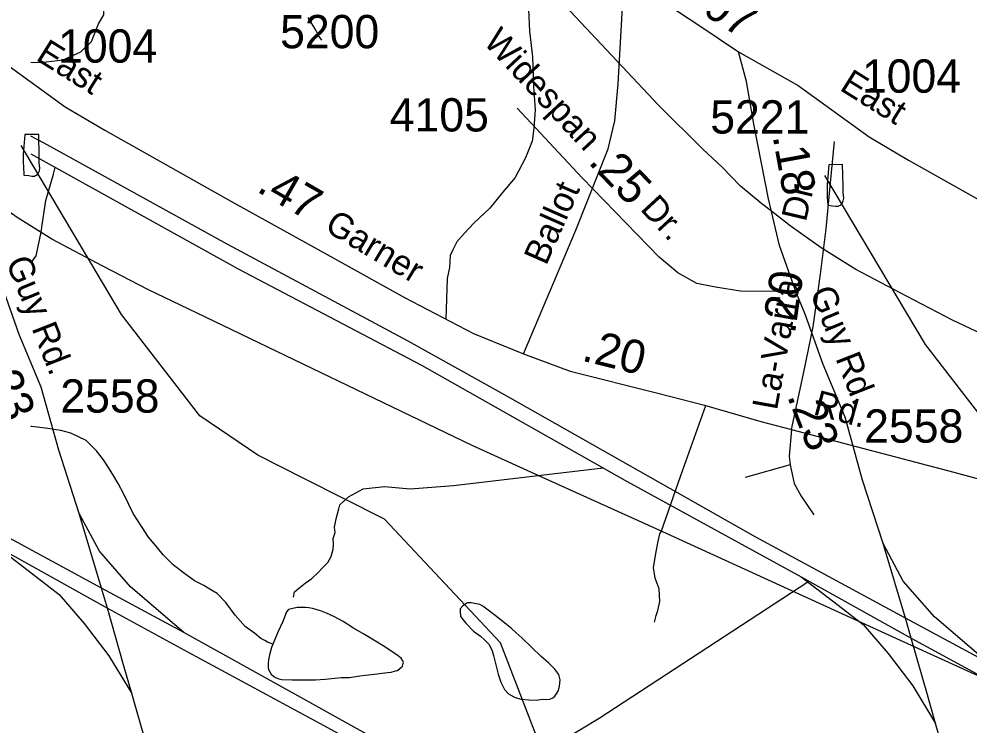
# Model space of a CAD drawing. Extents: x 2169602 to 2449496, y 721995 to 810662.
# Drawn here: x 2382070 to 2385634, y 765731 to 768381 of the extents above; entities that cross this region are included whole.
import ezdxf

# ---------------------------------------------------------------- set-up
doc = ezdxf.new("R2010")
doc.units = 0
doc.layers.add('Default', color=7, linetype='Continuous')

msp = doc.modelspace()

# ---------------------------------------------------------------- linework, layer by layer
at = {"layer": 'Default'}
for p, q in [((2382199.6, 767798.2), (2382205.6, 767824)), ((2384552.9, 766666.8), (2384647, 766929.6)), ((2384478.9, 766456.4), (2384552.9, 766666.8))]:
    msp.add_line(p, q, dxfattribs=at)
for points in [[(2384887.9, 767663.1), (2384856.4, 767687.8), (2384776.2, 767753.4), (2384707.8, 767825), (2384635.4, 767892.7), (2384468.8, 768057.9), (2384099.3, 768452.2), (2383723.7, 768848.4), (2383550.9, 769023.7), (2383458.6, 769117.2), (2383310.1, 769238.4), (2383207.7, 769300.1), (2383101.5, 769365.4), (2383005.3, 769423), (2382875.2, 769486.4), (2382114, 769885.3)], [(2383962.9, 767123.6), (2384159.1, 767588.5), (2384280.5, 767894.3), (2384305.6, 767999), (2384318.2, 768137.2), (2384360, 768891.2), (2384384.1, 769453), (2384383.2, 769500.7)], [(2382114, 768219.7), (2382150.3, 768218), (2382236.2, 768228), (2382302.2, 768257.7), (2382341.9, 768297.3), (2382368.3, 768363.4), (2382388.1, 768396.5), (2382388.1, 768436.1), (2382335.3, 768452.6), (2382206.5, 768495.6), (2382137.1, 768498.9)], [(2383981.2, 768415.7), (2383985.5, 768335.8), (2383996, 768239.8), (2384000.5, 768127.9), (2384006.9, 768040), (2384001.1, 767971.9), (2383995.3, 767922), (2383969.6, 767860), (2383931.9, 767785.7), (2383884.2, 767729.5), (2383836.6, 767671.3), (2383776.8, 767615.1), (2383740.8, 767577.1), (2383713, 767544.8), (2383697.2, 767514.8), (2383687.3, 767492.8), (2383685.4, 767448.8), (2383675.8, 767406.8), (2383671.7, 767254.3)], [(2384504.6, 768434.9), (2384617.1, 768360.5), (2384769.8, 768257.9)], [(2381754, 768370.7), (2381976.9, 768244), (2382243.7, 768051.4), (2382391.8, 767964.5), (2382864.7, 767697.4), (2383248.8, 767484.9), (2383516.6, 767336.2), (2383774.6, 767200.1), (2383962.9, 767123.6)], [(2383205.5, 768301.8), (2383193.6, 768319.8), (2383183.2, 768339.6), (2383155.1, 768387.3)], [(2384769.8, 768257.9), (2384992.7, 768131.2), (2385259.5, 767938.5), (2385407.6, 767851.6), (2385880.6, 767584.6), (2386264.6, 767372), (2386532.5, 767223.3), (2386790.4, 767087.2), (2386978.7, 767010.8)], [(2384893.1, 767659), (2384881.8, 767706.1), (2384827.9, 767980.4), (2384799.6, 768146.9), (2384769.8, 768257.9)], [(2382379.8, 766244.3), (2381818.6, 766548.8), (2380886.3, 767076.6), (2380513.8, 767283.9), (2379835.7, 767648.3), (2379148.2, 768027.4), (2379098.1, 768054.5)], [(2384984.9, 767358.4), (2384776.6, 767359.5), (2384682.5, 767374.1), (2384613.4, 767388.8), (2384542.2, 767428.6), (2384471.1, 767487.2), (2384182.3, 767784.6), (2383939.3, 768046.9)], [(2382136.2, 767795.1), (2382141.9, 767801.1), (2382146.2, 767811), (2382148.3, 767821.3), (2382146, 767843.1), (2382145.8, 767855.3), (2382145.8, 767867.1), (2382143.8, 767947.3), (2382091.9, 767947), (2382085.9, 767872.9), (2382086.1, 767840.8), (2382086.4, 767827), (2382088.2, 767795.1), (2382106.2, 767793.2), (2382118.1, 767790.9), (2382128, 767791.1), (2382132.1, 767793.3), (2382136.2, 767795.1)], [(2385395.6, 766131.5), (2384834.4, 766436), (2383902.1, 766963.8), (2383529.6, 767171.1), (2382851.5, 767535.5), (2382164.1, 767914.6), (2382114, 767941.7)], [(2383141.1, 766654.9), (2382965.8, 766743.1), (2382748.9, 766891.9), (2382454.8, 767271.8), (2382077.9, 767906.1)], [(2384967.9, 766840.1), (2385015.3, 767061.8), (2385049.6, 767225.7), (2385077.4, 767422.8), (2385098.8, 767593.2), (2385110.2, 767726.9), (2385129.1, 767921.6)], [(2382114, 767874.8), (2382891.8, 767443.3), (2383580.3, 767081), (2384351.5, 766645.4), (2385004.4, 766287.3)], [(2385152, 767682.2), (2385157.7, 767688.3), (2385162.1, 767698.2), (2385164.1, 767708.4), (2385161.9, 767730.3), (2385161.6, 767742.5), (2385161.6, 767754.3), (2385159.6, 767834.4), (2385107.7, 767834.2), (2385101.8, 767760.1), (2385102, 767728), (2385102.2, 767714.1), (2385104, 767682.2), (2385122.1, 767680.3), (2385134, 767678.1), (2385143.8, 767678.2), (2385147.9, 767680.5), (2385152, 767682.2)], [(2382114, 767464.3), (2382133.7, 767491.7), (2382153.5, 767580.9), (2382156.8, 767609), (2382170, 767699.8), (2382199.6, 767798.2)], [(2386341.5, 765606), (2386222.6, 765660.4), (2385827.8, 765842.7), (2385306.4, 766081), (2384545.7, 766428.8), (2384484.8, 766456.3), (2384045.6, 766654.9), (2383770.3, 766779.4), (2382736.4, 767278.6), (2382556.2, 767363.9), (2382383.8, 767453), (2382193.5, 767554.3), (2382063.2, 767635.5), (2381946.9, 767717.1), (2381872, 767775.9)], [(2386156.9, 766542.1), (2385981.6, 766630.2), (2385764.7, 766779), (2385470.7, 767159), (2385093.8, 767793.2)], [(2389357.3, 765493.2), (2389238.5, 765547.6), (2388843.6, 765729.8), (2388322.2, 765968.2), (2387561.5, 766315.9), (2387500.6, 766343.5), (2387061.4, 766542.1), (2386786.2, 766666.5), (2385752.3, 767165.8), (2385572, 767251), (2385399.7, 767340.2), (2385209.4, 767441.4), (2385079, 767522.7), (2384962.7, 767604.2), (2384887.9, 767663.1)], [(2384984.9, 767358.4), (2384923.6, 767531.2), (2384893.1, 767659)], [(2382296, 766524.7), (2382219.1, 766762.4), (2382153.2, 766999), (2382071.1, 767196.9), (2382005.1, 767382.3), (2381969, 767471.3)], [(2385311.8, 766411.9), (2385234.9, 766649.5), (2385169, 766886.2), (2385086.9, 767084.1), (2385021, 767269.4), (2384984.9, 767358.4)], [(2383962.9, 767123.6), (2384137.7, 767058.7), (2384466.2, 766977), (2384642, 766930.9), (2384853.4, 766870.2), (2384967.9, 766840.1)], [(2383021.9, 766033.7), (2383002, 766041.5), (2382991.6, 766047.6), (2382977.4, 766055.4), (2382953.6, 766075.2), (2382918, 766100.9), (2382881.5, 766142.9), (2382863, 766166.8), (2382845.4, 766190.6), (2382813.2, 766224.6), (2382789, 766238.4), (2382762.9, 766254.6), (2382728.9, 766272.3), (2382686.7, 766302.2), (2382648.7, 766331.9), (2382610.4, 766369.7), (2382584.1, 766401.6), (2382556.3, 766435.5), (2382530.2, 766475.2), (2382498, 766525), (2382481.6, 766559.1), (2382463.4, 766596.8), (2382441.4, 766637), (2382425.2, 766664.6), (2382405.1, 766696.9), (2382386.9, 766726.8), (2382360.8, 766760.3), (2382322.5, 766798.2), (2382292.6, 766812.1), (2382264.7, 766826), (2382226.9, 766835.8), (2382178.3, 766843.5), (2382118.5, 766851.4), (2382114, 766851.8)], [(2384967.9, 766840.1), (2384959.9, 766740.1), (2384963.5, 766707.1)], [(2384967.9, 766840.1), (2385577.5, 766679.6), (2386307.9, 766480.7), (2386610.8, 766395.9), (2386711.3, 766346.6)], [(2383269.7, 766542.1), (2383273.6, 766557.2), (2383305.8, 766587.6), (2383361.4, 766617.6), (2383440.7, 766626.1), (2383537, 766617.6), (2383699.8, 766630.4), (2384261.1, 766696.5)], [(2384963.5, 766707.1), (2384794.9, 766659.4)], [(2384963.5, 766707.1), (2384978.2, 766637.4), (2385003.8, 766589.7), (2385051.5, 766520)], [(2383827.8, 763157.7), (2383696.8, 763454.3), (2383670.8, 763605.7), (2383677.8, 763881.1), (2383883.8, 764506.8), (2383899.8, 764670.4), (2384005.8, 765022.6), (2384146.7, 765223.1), (2384145.9, 765465.8), (2384011.8, 765688.4), (2383876.9, 766038.9), (2383441.7, 766503.7), (2383141.1, 766654.9)], [(2382379.8, 766244.3), (2382296, 766524.7), (2382296, 766524.7)], [(2382688.6, 766077.6), (2382488.7, 766249.7), (2382371.4, 766383.7), (2382296, 766524.7)], [(2383099.2, 766210.5), (2383103.2, 766230.6), (2383125.1, 766248.5), (2383143, 766262.7), (2383169, 766280.8), (2383192.9, 766302.9), (2383208.8, 766321), (2383228.6, 766341), (2383240.5, 766363.1), (2383248.5, 766391.2), (2383250.4, 766409.1), (2383248.3, 766431.2), (2383256.1, 766453.2), (2383254.1, 766473.1), (2383260, 766505.1), (2383269.7, 766542.1)], [(2384454.4, 766116.4), (2384460, 766141.4), (2384466.9, 766160.9), (2384473.8, 766194.2), (2384471.1, 766241.4), (2384456.3, 766282.4), (2384450.1, 766322.5), (2384459.9, 766380.5), (2384467.2, 766414.6), (2384474.7, 766448.9), (2384478.9, 766456.4)], [(2385395.6, 766131.5), (2385311.9, 766411.8), (2385311.8, 766411.9)], [(2385704.4, 765964.8), (2385504.5, 766136.9), (2385387.2, 766270.9), (2385311.8, 766411.9)], [(2381988.5, 766400.2), (2382401.7, 766169.2)], [(2381988.5, 766400.2), (2382143.4, 766281.1), (2382220.9, 766220.4), (2382315, 766111.4), (2382407.1, 765990), (2382492.8, 765849.4)], [(2382964.6, 764996.3), (2382976.6, 765000.3), (2383018.5, 765024.4), (2383090.3, 765060.8), (2383191, 765087.9), (2383259.5, 765115.8), (2383343, 765160.7), (2383420.1, 765203.6), (2383602.1, 765325.7), (2383737, 765420), (2383906.2, 765522.8), (2384101, 765668.5), (2384246.6, 765756.3), (2385028.9, 766268.5)], [(2385004.4, 766287.3), (2385417.5, 766056.3)], [(2385004.4, 766287.3), (2385159.2, 766168.2), (2385236.7, 766107.5), (2385330.8, 765998.6), (2385422.9, 765877.2), (2385508.6, 765736.6)], [(2382401.7, 766169.2), (2382379.8, 766244.3)], [(2382688.6, 766077.6), (2382379.8, 766244.3)], [(2382401.7, 766169.2), (2382704.9, 766004.3), (2383213.4, 765728.9), (2383583.9, 765525.8), (2384094, 765232.6), (2384766.8, 764864), (2385293.7, 764587.2)], [(2382492.8, 765849.4), (2382462, 765956.5), (2382401.7, 766169.2)], [(2383021.9, 766033.7), (2383017.8, 766021.7), (2383009.6, 765993.7), (2383006.3, 765975.6), (2383004.3, 765963.3), (2383004.1, 765949.6), (2383004.3, 765945.5), (2383006.1, 765939.5), (2383016.4, 765921.7), (2383024.4, 765913.6), (2383032.2, 765909.6), (2383044.5, 765903.7), (2383056.4, 765901.9), (2383094.3, 765899.8), (2383128.3, 765899.9), (2383182.5, 765900.2), (2383218.6, 765902.5), (2383254.5, 765906.4), (2383278.7, 765908.9), (2383310, 765909), (2383348.2, 765915), (2383370.1, 765917.3), (2383403.9, 765921.5), (2383432.2, 765925.4), (2383452.1, 765927.6), (2383466.1, 765929.6), (2383482.1, 765933.6), (2383490.1, 765935.7), (2383499.9, 765943.5), (2383508.1, 765951.6), (2383511.8, 765961.6), (2383512, 765965.6), (2383510.2, 765971.5), (2383504.2, 765981.8), (2383487.8, 765993.6), (2383435.7, 766027.4), (2383365.6, 766070.9), (2383325.4, 766094.8), (2383285.6, 766118.7), (2383253.2, 766136.6), (2383223.3, 766150.5), (2383205.4, 766158.4), (2383185.1, 766164.3), (2383171.4, 766168), (2383157.3, 766170.1), (2383145.2, 766172), (2383129.2, 766172), (2383113.4, 766171.9), (2383097.4, 766167.8), (2383081.4, 766163.8), (2383073.2, 766155.7), (2383059.7, 766119.6), (2383041.8, 766081.8), (2383021.9, 766033.7)], [(2383766.3, 766188.9), (2383752.8, 766188.9), (2383734.6, 766178.7), (2383724.9, 766166.8), (2383724.9, 766156.6), (2383726.6, 766138.5), (2383746.9, 766112.7), (2383775.2, 766082.9), (2383801, 766064.8), (2383817.4, 766049), (2383833.6, 766033.1), (2383845.3, 766009), (2383849.6, 765991.3), (2383868.1, 765921.2), (2383877.9, 765891.3), (2383892, 765863.6), (2383906, 765847.7), (2383932, 765833.6), (2383954, 765827.9), (2383982.1, 765825.7), (2384010.4, 765823.9), (2384033.9, 765828), (2384043.8, 765826.1)], [(2384043.8, 765826.1), (2384062, 765828.2), (2384072.1, 765832.4), (2384079.9, 765838.5), (2384085.8, 765846.5), (2384094.2, 765860.3), (2384098.1, 765876.3), (2384099.6, 765900.4), (2384095.7, 765920.4), (2384079.9, 765940.3), (2384057.5, 765962.3), (2384029.2, 765988.1), (2383957, 766057.8), (2383933.3, 766077.7), (2383917.1, 766093.5), (2383898.6, 766107.6), (2383873, 766129.4), (2383850.8, 766145.3), (2383830.7, 766161.3), (2383810.6, 766176.9), (2383798.5, 766182.8), (2383778.9, 766187), (2383766.3, 766188.9)], [(2385417.5, 766056.3), (2385395.6, 766131.5)], [(2385704.4, 765964.8), (2385395.6, 766131.5)], [(2385334.7, 764626.5), (2384624, 765007.5), (2384002.4, 765345.7), (2383538.3, 765605.4), (2383105.1, 765846.2), (2382688.6, 766077.6)], [(2385417.5, 766056.3), (2385720.7, 765891.5), (2386229.3, 765616.1), (2386599.7, 765413), (2387109.8, 765119.8), (2387782.6, 764751.2), (2388309.5, 764474.4)], [(2385508.6, 765736.6), (2385477.8, 765843.6), (2385417.5, 766056.3)], [(2383023.2, 763386.5), (2382942.3, 763795.2), (2382859.6, 764199.4), (2382796.8, 764511.4), (2382739.3, 764817.2), (2382680.7, 765202.5), (2382636.7, 765363.8), (2382575, 765564.9), (2382492.8, 765849.4)], [(2386039, 763273.7), (2385958.1, 763682.4), (2385875.4, 764086.6), (2385812.6, 764398.6), (2385755.1, 764704.4), (2385696.5, 765089.7), (2385652.6, 765251), (2385590.8, 765452), (2385508.6, 765736.6)]]:
    msp.add_lwpolyline(points, dxfattribs=at)

# ---------------------------------------------------------------- texts
for s, height, rotation, p in [('.07', 125, 327.4651, (2384588.3, 768429)), ('Widespan', 95, 313.0498, (2383808.5, 768292.2)), ('East', 95, 327.9687, (2382129.1, 768229.5)), ('East', 95, 327.9687, (2385144.9, 768116.7)), ('.18', 125, 280.3012, (2384897, 767941)), ('.25', 125, 313.8101, (2384202.6, 767841.7)), ('.47', 125, 330.1053, (2382957.4, 767735.7)), ('Ballot', 95, 66.2021, (2384047.6, 767452.6)), ('Dr.', 95, 76.6801, (2385021.7, 767616.8)), ('Dr.', 95, 312.7872, (2384397.4, 767666)), ('Garner', 95, 329.0473, (2383211.9, 767589)), ('Guy', 95, 292.5499, (2382019.3, 767468.5)), ('.20', 125, 81.9616, (2384981, 767196.8)), ('La-Varra', 95, 79.7814, (2384913.5, 766909.7)), ('Guy', 95, 292.5499, (2385035.1, 767355.7)), ('Rd.', 95, 291.4754, (2382116.2, 767220.6)), ('.20', 125, 346.0401, (2384177.4, 767099.5)), ('Rd.', 95, 291.4754, (2385132, 767107.7)), ('.23', 125, 291.4754, (2381934.6, 767078.3)), ('Rd.', 95, 344.6937, (2385045.7, 766897.8)), ('.23', 125, 291.4754, (2384950.4, 766965.5))]:
    msp.add_text(s, height=height, rotation=rotation, dxfattribs=at).set_placement(p)
for s, p in [('5200', (2383049.6, 768271.4)), ('1004', (2382216.5, 768217.3)), ('1004', (2385232.4, 768104.5)), ('4105', (2383460.9, 767959)), ('5221', (2384663.4, 767951.1)), ('2558', (2382225, 766903.4)), ('2558', (2385240.8, 766790.6))]:
    msp.add_text(s, height=125, dxfattribs=at).set_placement(p)

doc.saveas('drawing.dxf')
